(* Logix 5000 project; controller MVI56DFCM_v13 vendor 1 type 14 code 51 rev 13.25; software revision 13.04 *)

TASK MainTask (continuous, watchdog 500 ms) : MainProgram

MODULES
   Local : vendor 1 type 14 code 51 (ICP 0, rev 13.25)
      DFCM : vendor 1 type 0 code 15 (ICP 1, rev 1.1, Output RPI 5 ms)
END_MODULES

TYPE DFCMBlkStat :   // This object is used to store the block transfer statistics for the MVI56-DFCM module.
STRUCT
   Read : INT;   // Total number of read block transfers
   Write : INT;   // Total number of write block transfers
   Parse : INT;   // Total number of blocks parsed
   Event : INT;   // Total number of event blocks received
   Cmd : INT;   // Total number of command blocks received
   Err : INT;   // Total number of block transfer errors
END_STRUCT
END_TYPE

TYPE DFCMCmd :   // This object is used to contain the attributes to define a master command. An array of these objects is used for each port.
STRUCT
   Enable : INT;   // 0=Disable,1=Continuous,2=Event Command
   IntAddress : INT;   // Module's internal address associated with the command
   PollInt : INT;   // Minimum number of seconds between issuance of command (0-65535 Sec)
   Count : INT;   // Number of registers associated with the command
   Swap : INT;   // Swap code used with command
   Node : INT;   // Address of device to interface with on the DF1 network
   Func : INT;   // DF1 function code as defined for MVI56-DFCM module
   Parameter_1 : INT;   // First parameter for function
   Parameter_2 : INT;   // Second parameter for function
   Parameter_3 : INT;   // Third parameter for function
   Parameter_4 : INT;   // Fourth parameter for function
END_STRUCT
END_TYPE

TYPE DFCMCmdControl :   // This object contains the data types that apply to the command control configuration /trigger bits of the feature.
STRUCT
   TriggerCmdCntrl : BOOL;   // Trigger command control. User application will activate this trigger
   NumberOfCommands : INT;   // Number of commands per block (1 to 6)
   PortNumber : INT;   // MVI56-DFCM Port Number of master port (1 or 2)
   CommandIndex : INT[6];   // Stores the command indexes for command control
   CmdsAddedToQueue : INT;   // Number of commands added to queue
   CmdControlBlockID : INT;   // Temporary variable to calculate control block ID
   CmdCntrlPending : BOOL;   // Auxilary control command-prevents a second request before acknowledgment is received
END_STRUCT
END_TYPE

TYPE DFCMCONFIG :   // This object contains the data types that apply to the configuration of the module.
STRUCT
   ModDef : DFCMModule;   // Module Definition
   Port1 : DFCMPort;   // Port 1 configuration settings
   Port2 : DFCMPort;   // Port 2 configuration settings
   Port1MasterCmd : DFCMCmd[100];   // Master commands for Port 1 (ignore if port is configured for slave mode)
   Port2MasterCmd : DFCMCmd[100];   // Master commands for Port 2 (ignore if port is configured for slave mode)
END_STRUCT
END_TYPE

TYPE DFCMCONTROL :   // Stores control registers used by the processor to rerquest special tasks from the module.
STRUCT
   WarmBoot : BOOL;   // Warm Boot
   ColdBoot : BOOL;   // Cold Boot
   BootTimer : TIMER;   // Boot Timer
   CmdControl : DFCMCmdControl;   // Allows for a disabled command to be sent to a device
   EventCmd : DFCMEventCmd;   // Allows a command defined in ladder to be sent to a device
   SlaveControl : DFCMSlaveControl;   // Control Slave Polling for Slave Status
END_STRUCT
END_TYPE

TYPE DFCMDATA :   // Contains Read Data (data read from the module to the processor) and Write Data (data written from the processor
STRUCT
   ReadData : INT[600];   // Data read from the module to the processor
   WriteData : INT[600];   // Data written from the processor to the module
END_STRUCT
END_TYPE

TYPE DFCMDataFileMap :   // DFCM Data File Mapping (1-50)
STRUCT
   IntDBAddr : INT;   // Internal Database Address Used by Mapping
   DataFileNumber : INT;   // Data File Number to Re-Direct in Command
   ElementNumber : INT;   // 1st Element Number to Start Address Offset
   ElenentLength : INT;   // Number of Elements in Range From Element Number
END_STRUCT
END_TYPE

TYPE DFCMEventCmd :   // This object contains the data types that apply to the event control configuration /trigger bits of the feature.
STRUCT
   EventCmdTrigger : BOOL;   // Trigger for event command. User ladder must set this bit to initiate event command
   EventCmdPending : BOOL;   // Set after the ladder has sent an event cmd to the module and is waiting for the status to be retur ned
   PortNumber : INT;   // Module master port number associated to this request (1 or 2)
   InternalDBAddress : INT;   // Internal database address
   PointCount : INT;   // Number of points for this command
   SwapCode : INT;   // Swap code (0= no swap, 1=swap words, 2=swap words and bytes, 3=swap bytes)
   SlaveAddress : INT;   // Slave target modbus address
   FunctioinCode : INT;   // Function Code
   Parameter1 : INT;   // Firrst Parameter for the function
   Parameter2 : INT;   // Second Parameter for the function
   Parameter3 : INT;   // Third Parameter for the function
   Parameter4 : INT;   // Fourth Parameter for the function
   EventCmdStatusReturned : INT;   // (0=Fail, 1=Success)
   EventBlockID : INT;   // Temporay variable to calculate event block ID
END_STRUCT
END_TYPE

TYPE DFCMModule :   // This object contains the information used to define the data movement between the module and the processor.
STRUCT
   WriteStartReg : INT;   // Start reg to transfer from PLC to module
   WriteRegCnt : INT;   // Number of registers to write from PLC
   ReadStartReg : INT;   // Start reg to transfer from module to PLC
   ReadRegCnt : INT;   // Number of registers to transfer from module
   BPFail : INT;   // Determines module operation if BP fails 0=continue,>0=number of retries before comm shutdown
   ErrStatPtr : INT;   // Internal DB start register for status data (-1=Ignore)
END_STRUCT
END_TYPE

TYPE DFCMModuleDef :   // This object contains the data types that apply to the operation of the module.
STRUCT
   CONFIG : DFCMCONFIG;   // Module and port configuration
   DATA : DFCMDATA;   // DFCM data transferred between module and processor
   STATUS : DFCMSTATUS;   // Status information in each read block
   CONTROL : DFCMCONTROL;   // Optional requests from the processor to the module
   UTIL : DFCMUTIL;   // Variables for internal ladder usage - should not be accessed by user application
   P1DATAFILEMAP : DFCMDataFileMap[50];   // Port 1 Data File Mappings
   P2DATAFILEMAP : DFCMDataFileMap[50];   // Port 2 Data File Mappings
END_STRUCT
END_TYPE

TYPE DFCMPort :   // This object is used to define the attributes related to the DF1 port.
STRUCT
   Enabled : INT;   // O=Port Disabled,1=Port Enabled
   Type : INT;   // 0=Master, 1=Slave
   StationID : INT;   // 0-254 local station id for device emulated on this port
   Protocol : INT;   // 0=Full-duplex, 1=half-duplex
   TerminationType : INT;   // 0=BCC, 1=CRC
   Baudrate : INT;   // Baudrate for port (110 to 115.2K)
   Parity : INT;   // 0=None, 1=Odd, 2=Even, 3=Mark, 4=Space
   DataBits : INT;   // 5 to 8 data bits
   StopBits : INT;   // 1 or 2 stop bits
   MinResp : INT;   // 0-65535 mSec minimum time before response to request
   RTSOn : INT;   // 0-65535 mSec delay before data
   RTSOff : INT;   // 0-65535 mSec delay after data
   UseCTS : INT;   // 0=No, 1=Yes to use CTS modem line
   ENQDelay : INT;   // 0-65535 delay after ACK before sending ENQ request (half-duplex)
   CmdCount : INT;   // Command list count (Master)
   MinCmdDelay : INT;   // 0-65535 mSec minimum time between each command (Master)
   CmdErrPtr : INT;   // Internal DB location to place command error list (Master)
   RespTO : INT;   // 0-65535 mSec response timeout for command (Master)
   Retry_Count : INT;   // Retry count for failed request (Master)
   ErrorDelayCntr : INT;   // 0-65535 Command cycle count if error (Master)
   SlaveListPtr : INT;   // -1=No slave list in database, 0-4743=Reg start location for data (Master)
   SlaveListFreq : INT;   // 0=No slave list in database, 1-65535=cycle count for update (Master)
   FirstFile : INT;   // 0-100 First file to emulate in database (Slave)
   FileSize : INT;   // 0-1000 size of each file to emulate (Slave)
   FileOffset : INT;   // 0-4999 register offset into database where file emulation starts (Slave)
   DataFileMapCnt : INT;   // 0-50 Data File Mapping Count to Re-Direct data Reads and Writes (Slave)
END_STRUCT
END_TYPE

TYPE DFCMPortErrors :   // This object is used to store the port statistics for an MVI56-DFCM port.
STRUCT
   CmdReq : INT;   // Total number of command list requests sent
   CmdResp : INT;   // Total number of command list responses received
   CmdErr : INT;   // Total number of command list errors
   Requests : INT;   // Total number of requests for port
   Responses : INT;   // Total number of responses for port
   ErrSent : INT;   // Total number of errors sent
   ErrRec : INT;   // Total number of errors received
END_STRUCT
END_TYPE

TYPE DFCMSlaveControl :   // Special block processing for Slave Control
STRUCT
   TriggerSlaveControl : BOOL;   // Trigger to Enable or Disable Slaves
   PortNumber : INT;   // Slave Address
   NumberOfSlaves : INT;   // Number of Slaves
   BlockNumber : INT;   // Block ID number
   SlaveIndexes : INT[200];   // Slave Indexes
   NumberOfSlavesProcessed : INT;   // Number of Slaves processed
   EnableSlaves : BOOL;   // Set 0 to Disable or 1 to Enable Slaves
   Port1Slave0Read : BOOL;   // Trigger to poll slave status
   Port1Slave128Read : BOOL;   // Trigger to poll slave status
   Port2Slave0Read : BOOL;   // Trigger to poll slave status
   Port2Slave128Read : BOOL;   // Trigger to poll slave status
END_STRUCT
END_TYPE

TYPE DFCMSlavePollStatus :   // This object contains all of the Slave Polling status (used when the port is used as a master)
STRUCT
   P1Slaves : INT[256];   // Slave status after polling for slave staus information
   P2Slaves : INT[256];   // Slave status after polling for slave staus information
END_STRUCT
END_TYPE

TYPE DFCMSTATUS :   // This status data is returned on each read block and can be used to detect proper module operation.
STRUCT
   PassCnt : INT;   // Program cycle counter
   Product : INT[2];   // Product Name
   Rev : INT[2];   // Revision Level Number
   OP : INT[2];   // Operating Level Number
   Run : INT[2];   // Run Number
   PrtErrs : DFCMPortErrors[2];   // Port error statistics
   BlkErrs : DFCMBlkStat;   // Block transfer statistics
   P1CErr : INT;   // Port 1 current error/index
   P1LErr : INT;   // Port 1 last error/index
   P2CErr : INT;   // Port 2 current error/index
   P2LErr : INT;   // Port 2 current error/index
   SlavePollStatus : DFCMSlavePollStatus;   // Request slave poll status for the port (MASTER)
END_STRUCT
END_TYPE

TYPE DFCMUTIL :   // This object contains the data types that apply to the utility of the module.
STRUCT
   BPLastRead : INT;   // Index of last read block
   BPLastWrite : INT;   // Index of last write block
   BlockIndex : INT;   // Computed block offset for data table
   ReadDataSize : DINT;   // Size of Read Data Array
   MaxReadBlock : DINT;   // Maximum Read Block
   WriteDataSize : DINT;   // Size of Write Data Array
   MaxWriteBlock : DINT;   // Maximum Write Block
   RBTSremainder : INT;   // Contains remainder from Read Data array size divided by the block size
   WBTSremainder : INT;   // Contains remainder from Read Data array size divided by the block size
END_STRUCT
END_TYPE

VAR_GLOBAL   (* controller tags *)
   DFCM : DFCMModuleDef;
   MJFAULTS : DINT[12];
END_VAR

PROGRAM MainProgram   (* routine attr 65 MainRoutine *)

ROUTINE MainRoutine   (* ladder *)
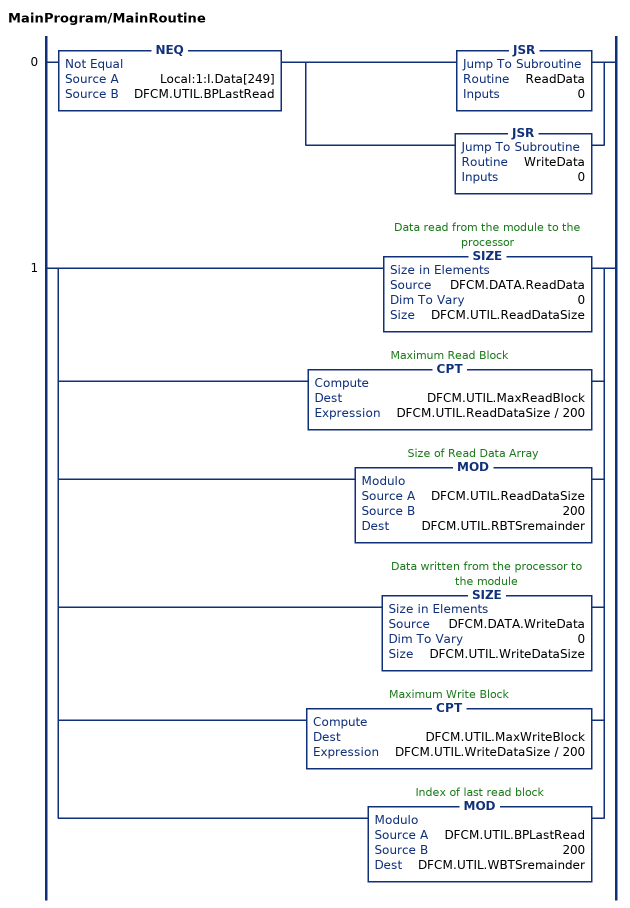
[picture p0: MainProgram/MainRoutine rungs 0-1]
   0: NEQ(Local:1:I.Data[249],DFCM.UTIL.BPLastRead)[JSR(ReadData,0) ,JSR(WriteData,0) ];
   1: [SIZE(DFCM.DATA.ReadData,0,DFCM.UTIL.ReadDataSize) ,CPT(DFCM.UTIL.MaxReadBlock,DFCM.UTIL.ReadDataSize / 200) ,MOD(DFCM.UTIL.ReadDataSize,200,DFCM.UTIL.RBTSremainder) ,SIZE(DFCM.DATA.WriteData,0,DFCM.UTIL.WriteDataSize) ,CPT(DFCM.UTIL.MaxWriteBlock,DFCM.UTIL.WriteDataSize / 200) ,MOD(DFCM.UTIL.BPLastRead,200,DFCM.UTIL.WBTSremainder) ];
END_ROUTINE

ROUTINE ReadData   (* ladder *)
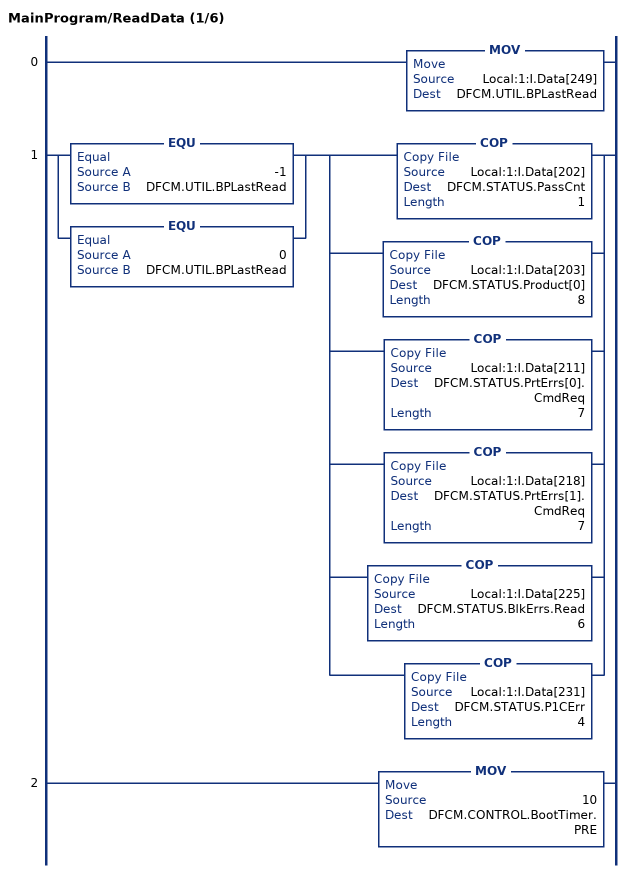
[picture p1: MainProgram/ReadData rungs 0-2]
   0: MOV(Local:1:I.Data[249],DFCM.UTIL.BPLastRead);
   1: [EQU(-1,DFCM.UTIL.BPLastRead) ,EQU(0,DFCM.UTIL.BPLastRead) ][COP(Local:1:I.Data[202],DFCM.STATUS.PassCnt,1) ,COP(Local:1:I.Data[203],DFCM.STATUS.Product[0],8) ,COP(Local:1:I.Data[211],DFCM.STATUS.PrtErrs[0].CmdReq,7) ,COP(Local:1:I.Data[218],DFCM.STATUS.PrtErrs[1].CmdReq,7) ,COP(Local:1:I.Data[225],DFCM.STATUS.BlkErrs.Read,6) ,COP(Local:1:I.Data[231],DFCM.STATUS.P1CErr,4) ];
   2: MOV(10,DFCM.CONTROL.BootTimer.PRE);
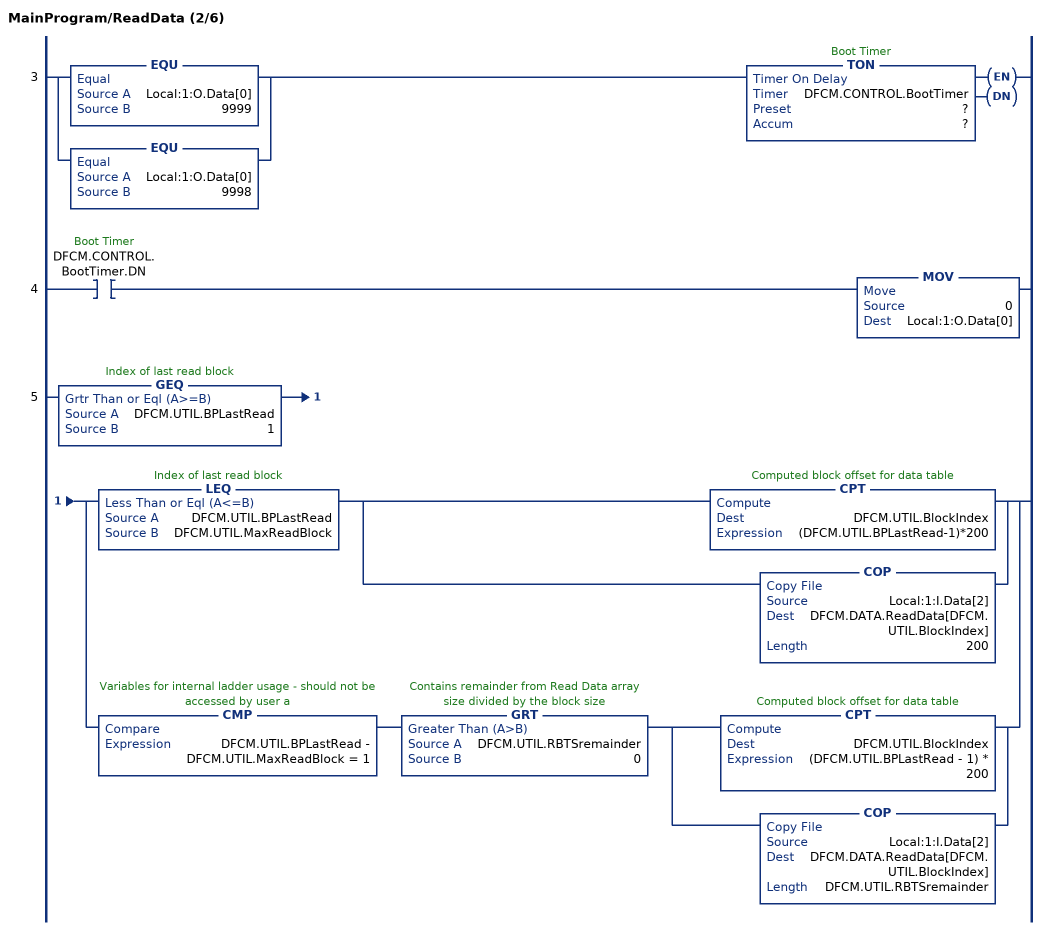
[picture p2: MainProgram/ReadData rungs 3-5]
   3: [EQU(Local:1:O.Data[0],9999) ,EQU(Local:1:O.Data[0],9998) ]TON(DFCM.CONTROL.BootTimer,?,?);
   4: XIC(DFCM.CONTROL.BootTimer.DN)MOV(0,Local:1:O.Data[0]);
   5: GEQ(DFCM.UTIL.BPLastRead,1)[LEQ(DFCM.UTIL.BPLastRead,DFCM.UTIL.MaxReadBlock) [CPT(DFCM.UTIL.BlockIndex,(DFCM.UTIL.BPLastRead-1)*200) ,COP(Local:1:I.Data[2],DFCM.DATA.ReadData[DFCM.UTIL.BlockIndex],200) ] ,CMP(DFCM.UTIL.BPLastRead - DFCM.UTIL.MaxReadBlock = 1) GRT(DFCM.UTIL.RBTSremainder,0) [CPT(DFCM.UTIL.BlockIndex,(DFCM.UTIL.BPLastRead - 1) * 200) ,COP(Local:1:I.Data[2],DFCM.DATA.ReadData[DFCM.UTIL.BlockIndex],DFCM.UTIL.RBTSremainder) ] ];
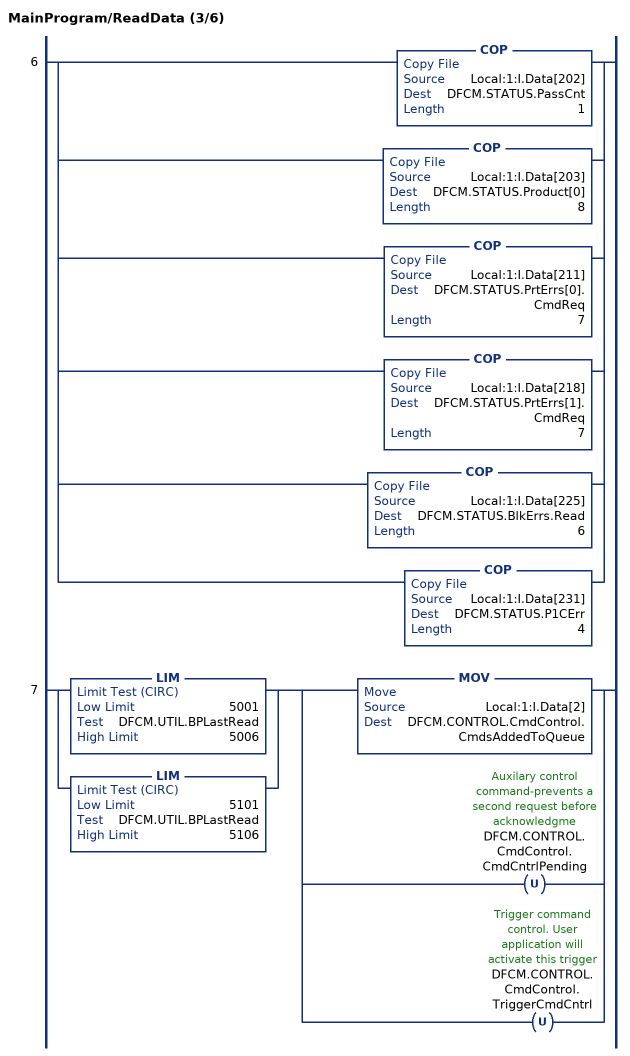
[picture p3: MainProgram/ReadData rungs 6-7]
   6: [COP(Local:1:I.Data[202],DFCM.STATUS.PassCnt,1) ,COP(Local:1:I.Data[203],DFCM.STATUS.Product[0],8) ,COP(Local:1:I.Data[211],DFCM.STATUS.PrtErrs[0].CmdReq,7) ,COP(Local:1:I.Data[218],DFCM.STATUS.PrtErrs[1].CmdReq,7) ,COP(Local:1:I.Data[225],DFCM.STATUS.BlkErrs.Read,6) ,COP(Local:1:I.Data[231],DFCM.STATUS.P1CErr,4) ];
   7: [LIM(5001,DFCM.UTIL.BPLastRead,5006) ,LIM(5101,DFCM.UTIL.BPLastRead,5106) ][MOV(Local:1:I.Data[2],DFCM.CONTROL.CmdControl.CmdsAddedToQueue) ,OTU(DFCM.CONTROL.CmdControl.CmdCntrlPending) ,OTU(DFCM.CONTROL.CmdControl.TriggerCmdCntrl) ];
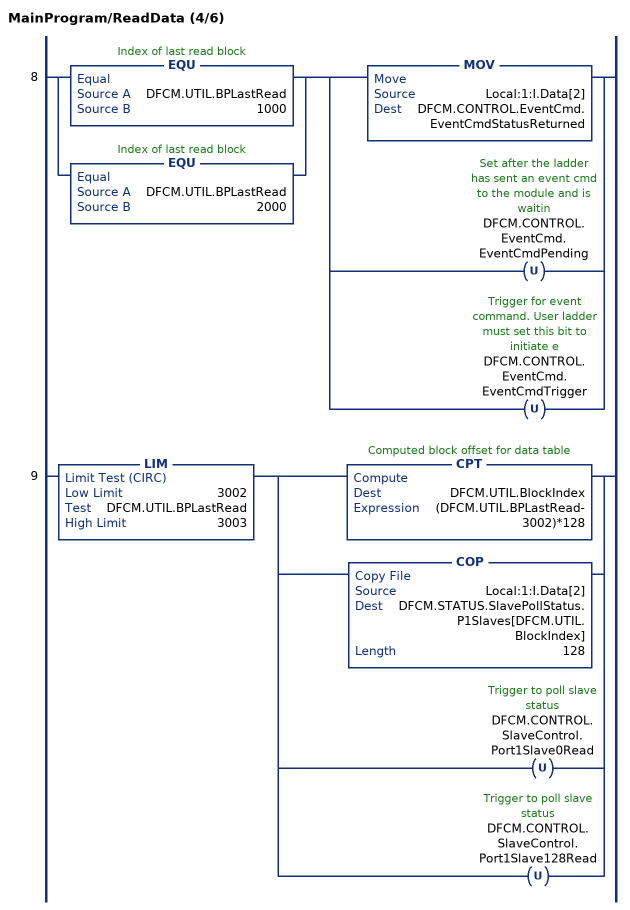
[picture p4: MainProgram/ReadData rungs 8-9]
   8: [EQU(DFCM.UTIL.BPLastRead,1000) ,EQU(DFCM.UTIL.BPLastRead,2000) ][MOV(Local:1:I.Data[2],DFCM.CONTROL.EventCmd.EventCmdStatusReturned) ,OTU(DFCM.CONTROL.EventCmd.EventCmdPending) ,OTU(DFCM.CONTROL.EventCmd.EventCmdTrigger) ];
   9: LIM(3002,DFCM.UTIL.BPLastRead,3003)[CPT(DFCM.UTIL.BlockIndex,(DFCM.UTIL.BPLastRead-3002)*128) ,COP(Local:1:I.Data[2],DFCM.STATUS.SlavePollStatus.P1Slaves[DFCM.UTIL.BlockIndex],128) ,OTU(DFCM.CONTROL.SlaveControl.Port1Slave0Read) ,OTU(DFCM.CONTROL.SlaveControl.Port1Slave128Read) ];
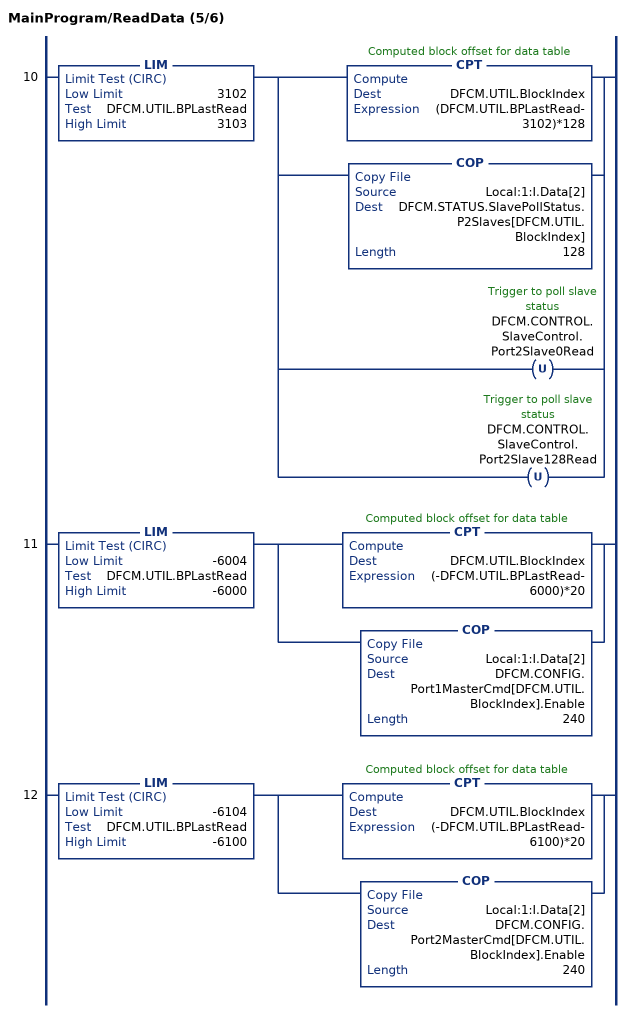
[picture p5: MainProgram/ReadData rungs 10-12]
   10: LIM(3102,DFCM.UTIL.BPLastRead,3103)[CPT(DFCM.UTIL.BlockIndex,(DFCM.UTIL.BPLastRead-3102)*128) ,COP(Local:1:I.Data[2],DFCM.STATUS.SlavePollStatus.P2Slaves[DFCM.UTIL.BlockIndex],128) ,OTU(DFCM.CONTROL.SlaveControl.Port2Slave0Read) ,OTU(DFCM.CONTROL.SlaveControl.Port2Slave128Read) ];
   11: LIM(-6004,DFCM.UTIL.BPLastRead,-6000)[CPT(DFCM.UTIL.BlockIndex,(-DFCM.UTIL.BPLastRead-6000)*20) ,COP(Local:1:I.Data[2],DFCM.CONFIG.Port1MasterCmd[DFCM.UTIL.BlockIndex].Enable,240) ];
   12: LIM(-6104,DFCM.UTIL.BPLastRead,-6100)[CPT(DFCM.UTIL.BlockIndex,(-DFCM.UTIL.BPLastRead-6100)*20) ,COP(Local:1:I.Data[2],DFCM.CONFIG.Port2MasterCmd[DFCM.UTIL.BlockIndex].Enable,240) ];
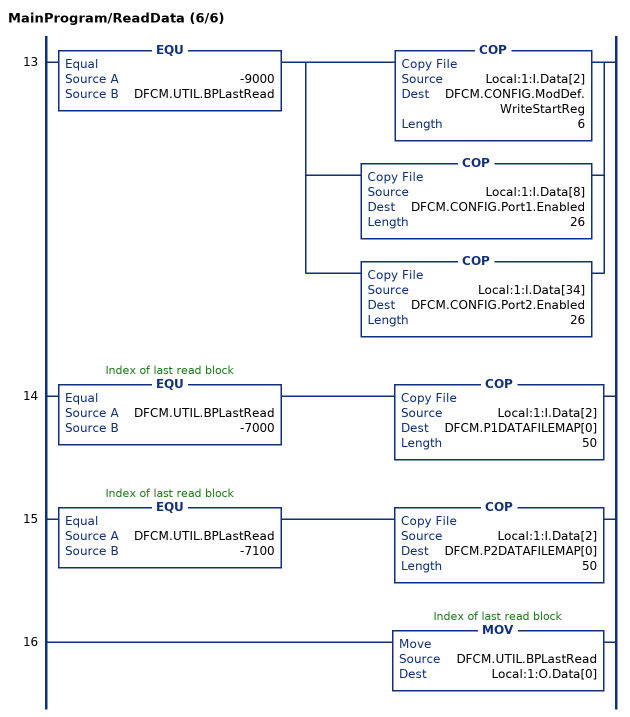
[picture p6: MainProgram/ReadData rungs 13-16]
   13: EQU(-9000,DFCM.UTIL.BPLastRead)[COP(Local:1:I.Data[2],DFCM.CONFIG.ModDef.WriteStartReg,6) ,COP(Local:1:I.Data[8],DFCM.CONFIG.Port1.Enabled,26) ,COP(Local:1:I.Data[34],DFCM.CONFIG.Port2.Enabled,26) ];
   14: EQU(DFCM.UTIL.BPLastRead,-7000)COP(Local:1:I.Data[2],DFCM.P1DATAFILEMAP[0],50);
   15: EQU(DFCM.UTIL.BPLastRead,-7100)COP(Local:1:I.Data[2],DFCM.P2DATAFILEMAP[0],50);
   16: MOV(DFCM.UTIL.BPLastRead,Local:1:O.Data[0]);
END_ROUTINE

ROUTINE WriteData   (* ladder *)
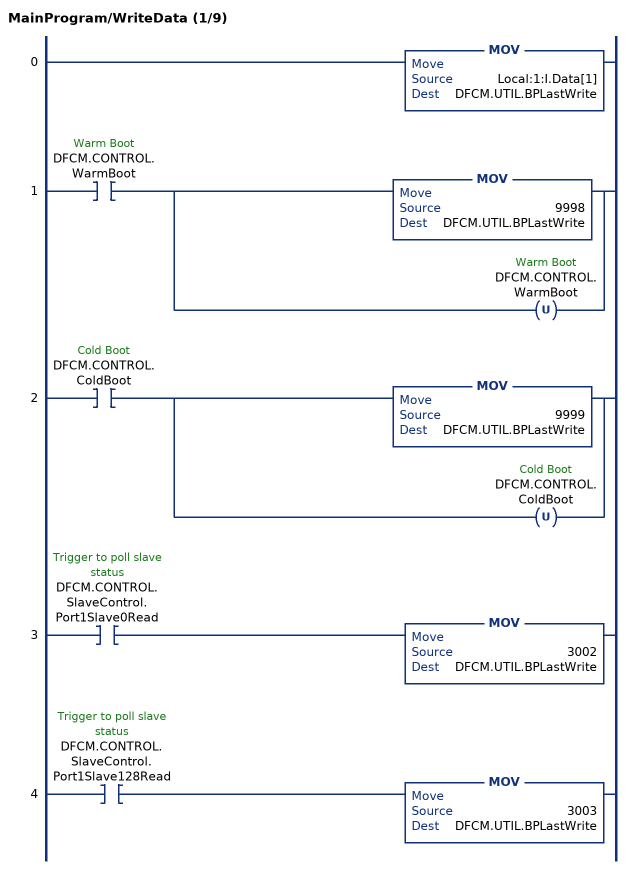
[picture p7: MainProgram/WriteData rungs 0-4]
   0: MOV(Local:1:I.Data[1],DFCM.UTIL.BPLastWrite);
   1: XIC(DFCM.CONTROL.WarmBoot)[MOV(9998,DFCM.UTIL.BPLastWrite) ,OTU(DFCM.CONTROL.WarmBoot) ];
   2: XIC(DFCM.CONTROL.ColdBoot)[MOV(9999,DFCM.UTIL.BPLastWrite) ,OTU(DFCM.CONTROL.ColdBoot) ];
   3: XIC(DFCM.CONTROL.SlaveControl.Port1Slave0Read)MOV(3002,DFCM.UTIL.BPLastWrite);
   4: XIC(DFCM.CONTROL.SlaveControl.Port1Slave128Read)MOV(3003,DFCM.UTIL.BPLastWrite);
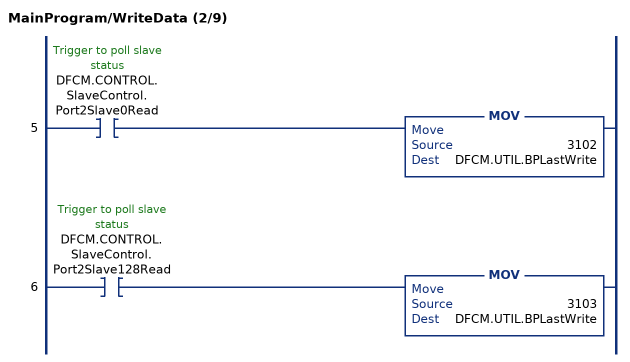
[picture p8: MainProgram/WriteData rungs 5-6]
   5: XIC(DFCM.CONTROL.SlaveControl.Port2Slave0Read)MOV(3102,DFCM.UTIL.BPLastWrite);
   6: XIC(DFCM.CONTROL.SlaveControl.Port2Slave128Read)MOV(3103,DFCM.UTIL.BPLastWrite);
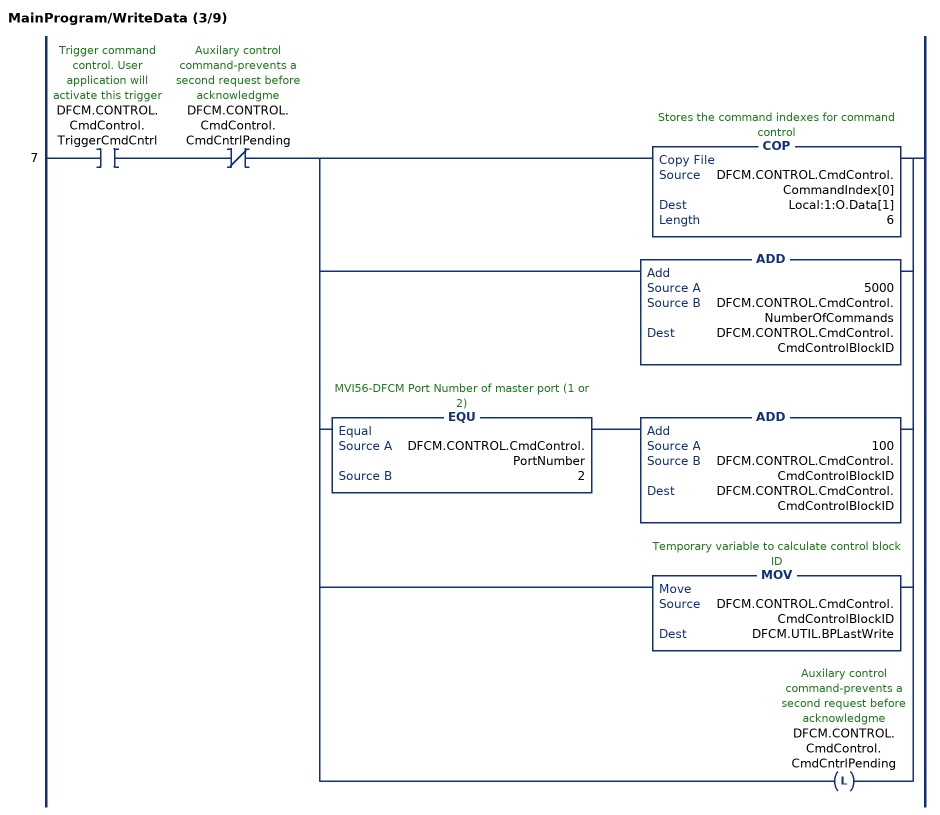
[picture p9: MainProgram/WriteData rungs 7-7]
   7: XIC(DFCM.CONTROL.CmdControl.TriggerCmdCntrl)XIO(DFCM.CONTROL.CmdControl.CmdCntrlPending)[COP(DFCM.CONTROL.CmdControl.CommandIndex[0],Local:1:O.Data[1],6) ,ADD(5000,DFCM.CONTROL.CmdControl.NumberOfCommands,DFCM.CONTROL.CmdControl.CmdControlBlockID) ,EQU(DFCM.CONTROL.CmdControl.PortNumber,2) ADD(100,DFCM.CONTROL.CmdControl.CmdControlBlockID,DFCM.CONTROL.CmdControl.CmdControlBlockID) ,MOV(DFCM.CONTROL.CmdControl.CmdControlBlockID,DFCM.UTIL.BPLastWrite) ,OTL(DFCM.CONTROL.CmdControl.CmdCntrlPending) ];
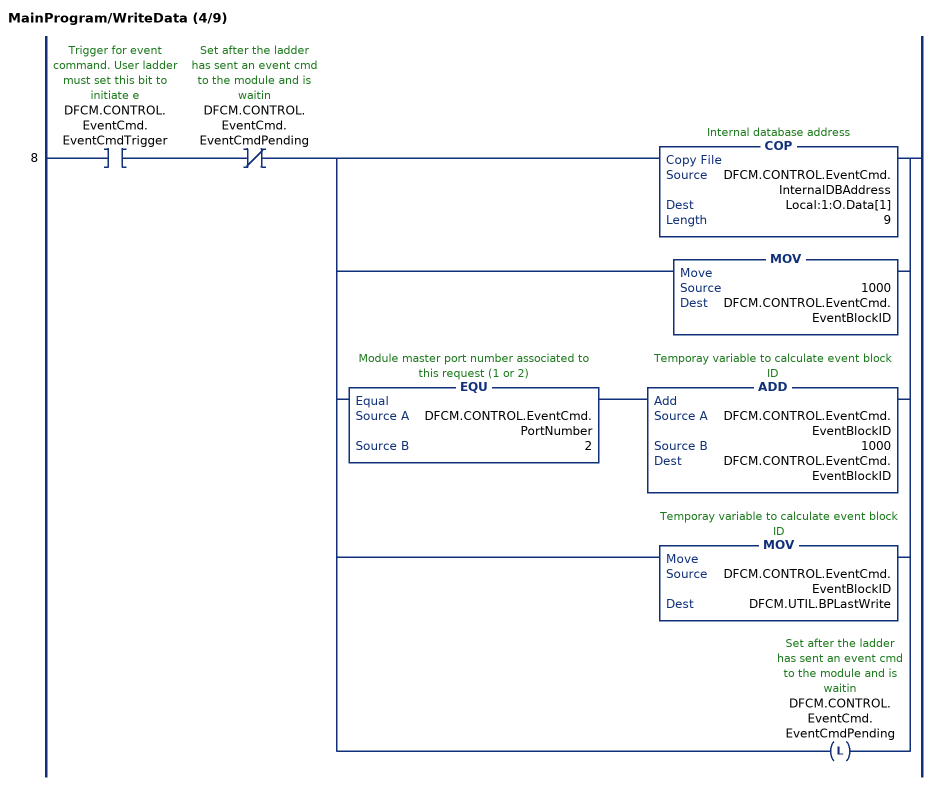
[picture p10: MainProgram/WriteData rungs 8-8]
   8: XIC(DFCM.CONTROL.EventCmd.EventCmdTrigger)XIO(DFCM.CONTROL.EventCmd.EventCmdPending)[COP(DFCM.CONTROL.EventCmd.InternalDBAddress,Local:1:O.Data[1],9) ,MOV(1000,DFCM.CONTROL.EventCmd.EventBlockID) ,EQU(DFCM.CONTROL.EventCmd.PortNumber,2) ADD(DFCM.CONTROL.EventCmd.EventBlockID,1000,DFCM.CONTROL.EventCmd.EventBlockID) ,MOV(DFCM.CONTROL.EventCmd.EventBlockID,DFCM.UTIL.BPLastWrite) ,OTL(DFCM.CONTROL.EventCmd.EventCmdPending) ];
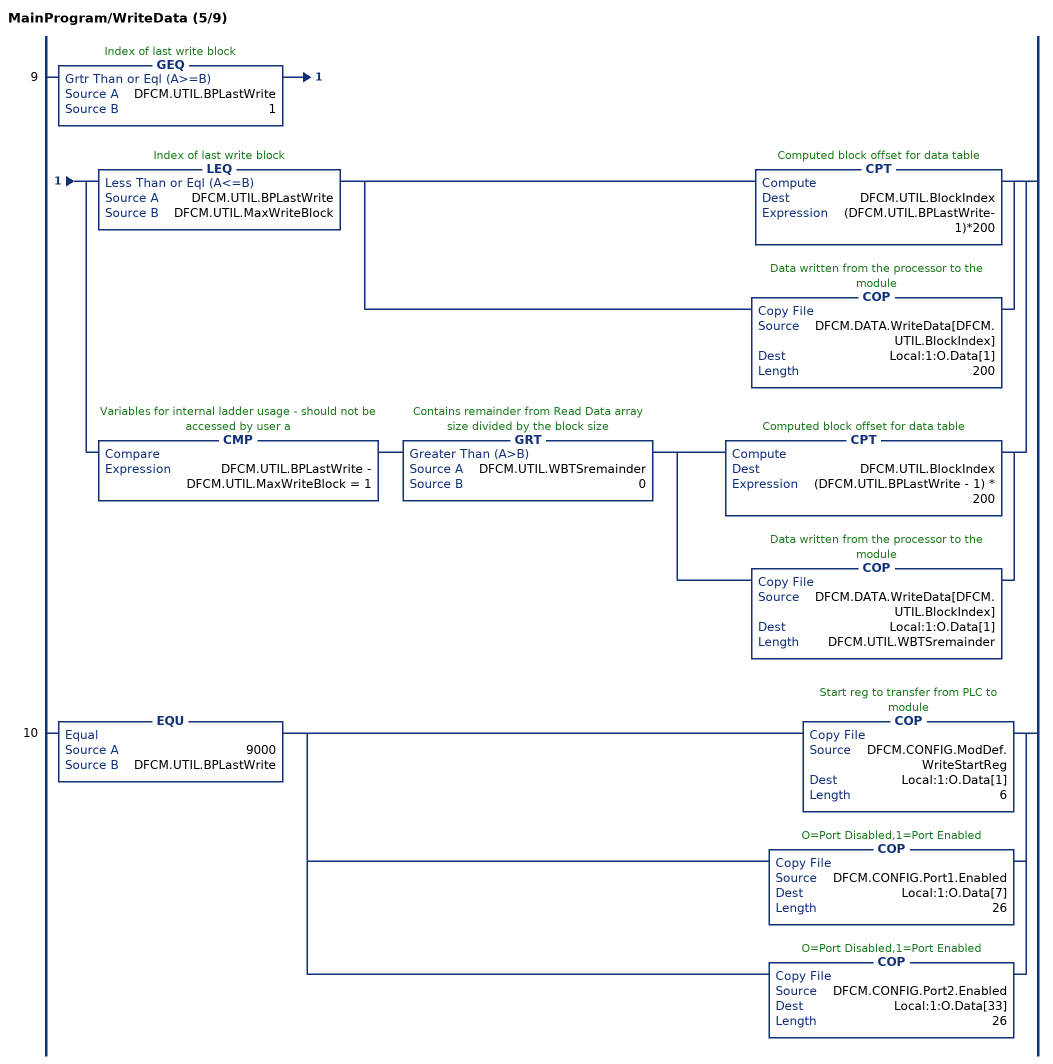
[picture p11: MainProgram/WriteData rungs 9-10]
   9: GEQ(DFCM.UTIL.BPLastWrite,1)[LEQ(DFCM.UTIL.BPLastWrite,DFCM.UTIL.MaxWriteBlock) [CPT(DFCM.UTIL.BlockIndex,(DFCM.UTIL.BPLastWrite-1)*200) ,COP(DFCM.DATA.WriteData[DFCM.UTIL.BlockIndex],Local:1:O.Data[1],200) ] ,CMP(DFCM.UTIL.BPLastWrite - DFCM.UTIL.MaxWriteBlock = 1) GRT(DFCM.UTIL.WBTSremainder,0) [CPT(DFCM.UTIL.BlockIndex,(DFCM.UTIL.BPLastWrite - 1) * 200) ,COP(DFCM.DATA.WriteData[DFCM.UTIL.BlockIndex],Local:1:O.Data[1],DFCM.UTIL.WBTSremainder) ] ];
   10: EQU(9000,DFCM.UTIL.BPLastWrite)[COP(DFCM.CONFIG.ModDef.WriteStartReg,Local:1:O.Data[1],6) ,COP(DFCM.CONFIG.Port1.Enabled,Local:1:O.Data[7],26) ,COP(DFCM.CONFIG.Port2.Enabled,Local:1:O.Data[33],26) ];
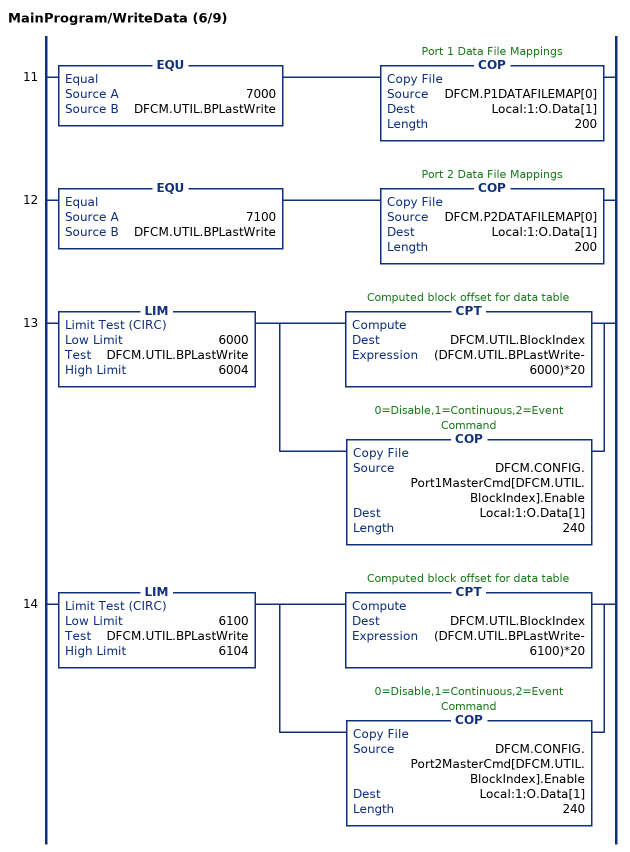
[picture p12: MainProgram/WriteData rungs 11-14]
   11: EQU(7000,DFCM.UTIL.BPLastWrite)COP(DFCM.P1DATAFILEMAP[0],Local:1:O.Data[1],200);
   12: EQU(7100,DFCM.UTIL.BPLastWrite)COP(DFCM.P2DATAFILEMAP[0],Local:1:O.Data[1],200);
   13: LIM(6000,DFCM.UTIL.BPLastWrite,6004)[CPT(DFCM.UTIL.BlockIndex,(DFCM.UTIL.BPLastWrite-6000)*20) ,COP(DFCM.CONFIG.Port1MasterCmd[DFCM.UTIL.BlockIndex].Enable,Local:1:O.Data[1],240) ];
   14: LIM(6100,DFCM.UTIL.BPLastWrite,6104)[CPT(DFCM.UTIL.BlockIndex,(DFCM.UTIL.BPLastWrite-6100)*20) ,COP(DFCM.CONFIG.Port2MasterCmd[DFCM.UTIL.BlockIndex].Enable,Local:1:O.Data[1],240) ];
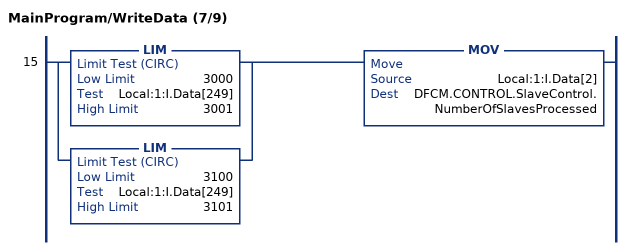
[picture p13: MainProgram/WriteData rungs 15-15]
   15: [LIM(3000,Local:1:I.Data[249],3001) ,LIM(3100,Local:1:I.Data[249],3101) ]MOV(Local:1:I.Data[2],DFCM.CONTROL.SlaveControl.NumberOfSlavesProcessed);
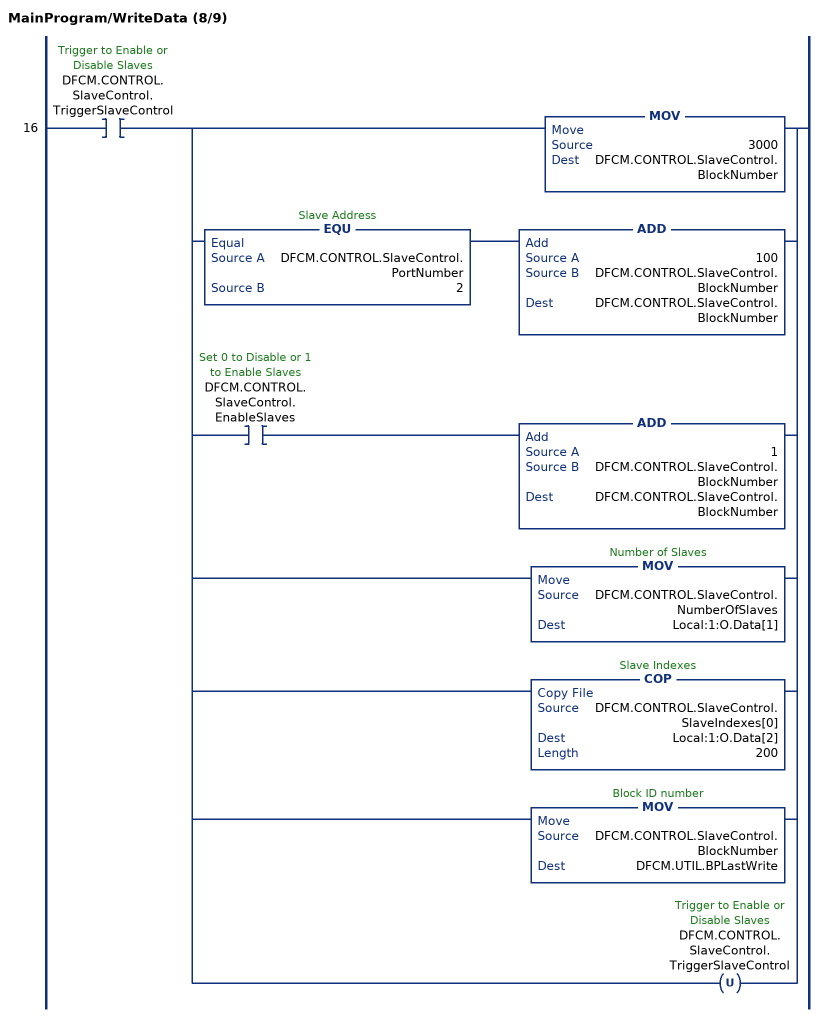
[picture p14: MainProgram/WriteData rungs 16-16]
   16: XIC(DFCM.CONTROL.SlaveControl.TriggerSlaveControl)[MOV(3000,DFCM.CONTROL.SlaveControl.BlockNumber) ,EQU(DFCM.CONTROL.SlaveControl.PortNumber,2) ADD(100,DFCM.CONTROL.SlaveControl.BlockNumber,DFCM.CONTROL.SlaveControl.BlockNumber) ,XIC(DFCM.CONTROL.SlaveControl.EnableSlaves) ADD(1,DFCM.CONTROL.SlaveControl.BlockNumber,DFCM.CONTROL.SlaveControl.BlockNumber) ,MOV(DFCM.CONTROL.SlaveControl.NumberOfSlaves,Local:1:O.Data[1]) ,COP(DFCM.CONTROL.SlaveControl.SlaveIndexes[0],Local:1:O.Data[2],200) ,MOV(DFCM.CONTROL.SlaveControl.BlockNumber,DFCM.UTIL.BPLastWrite) ,OTU(DFCM.CONTROL.SlaveControl.TriggerSlaveControl) ];
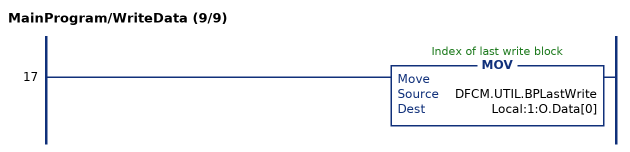
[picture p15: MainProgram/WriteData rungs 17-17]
   17: MOV(DFCM.UTIL.BPLastWrite,Local:1:O.Data[0]);
END_ROUTINE
END_PROGRAM

PROGRAM Startup   (* routine attr 65 PowerUp *)

ROUTINE PowerUp   (* ladder *)
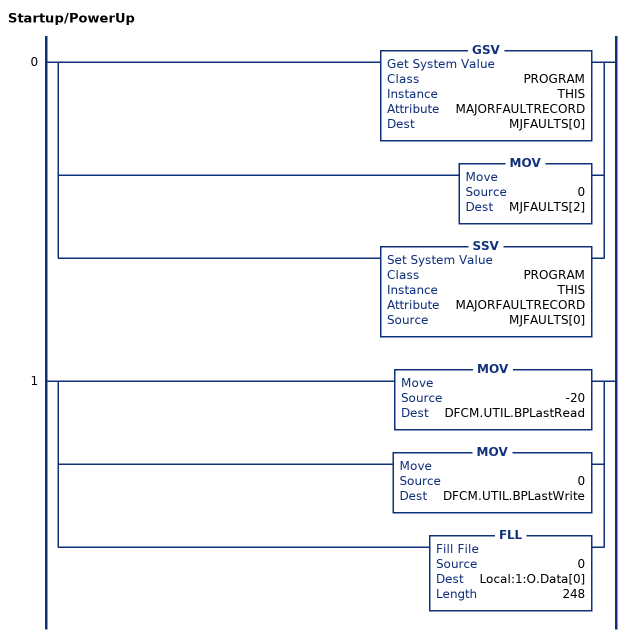
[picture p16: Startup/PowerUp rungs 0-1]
   0: [GSV(PROGRAM,THIS,MAJORFAULTRECORD,MJFAULTS[0]) ,MOV(0,MJFAULTS[2]) ,SSV(PROGRAM,THIS,MAJORFAULTRECORD,MJFAULTS[0]) ];
   1: [MOV(-20,DFCM.UTIL.BPLastRead) ,MOV(0,DFCM.UTIL.BPLastWrite) ,FLL(0,Local:1:O.Data[0],248) ];
END_ROUTINE
END_PROGRAM
